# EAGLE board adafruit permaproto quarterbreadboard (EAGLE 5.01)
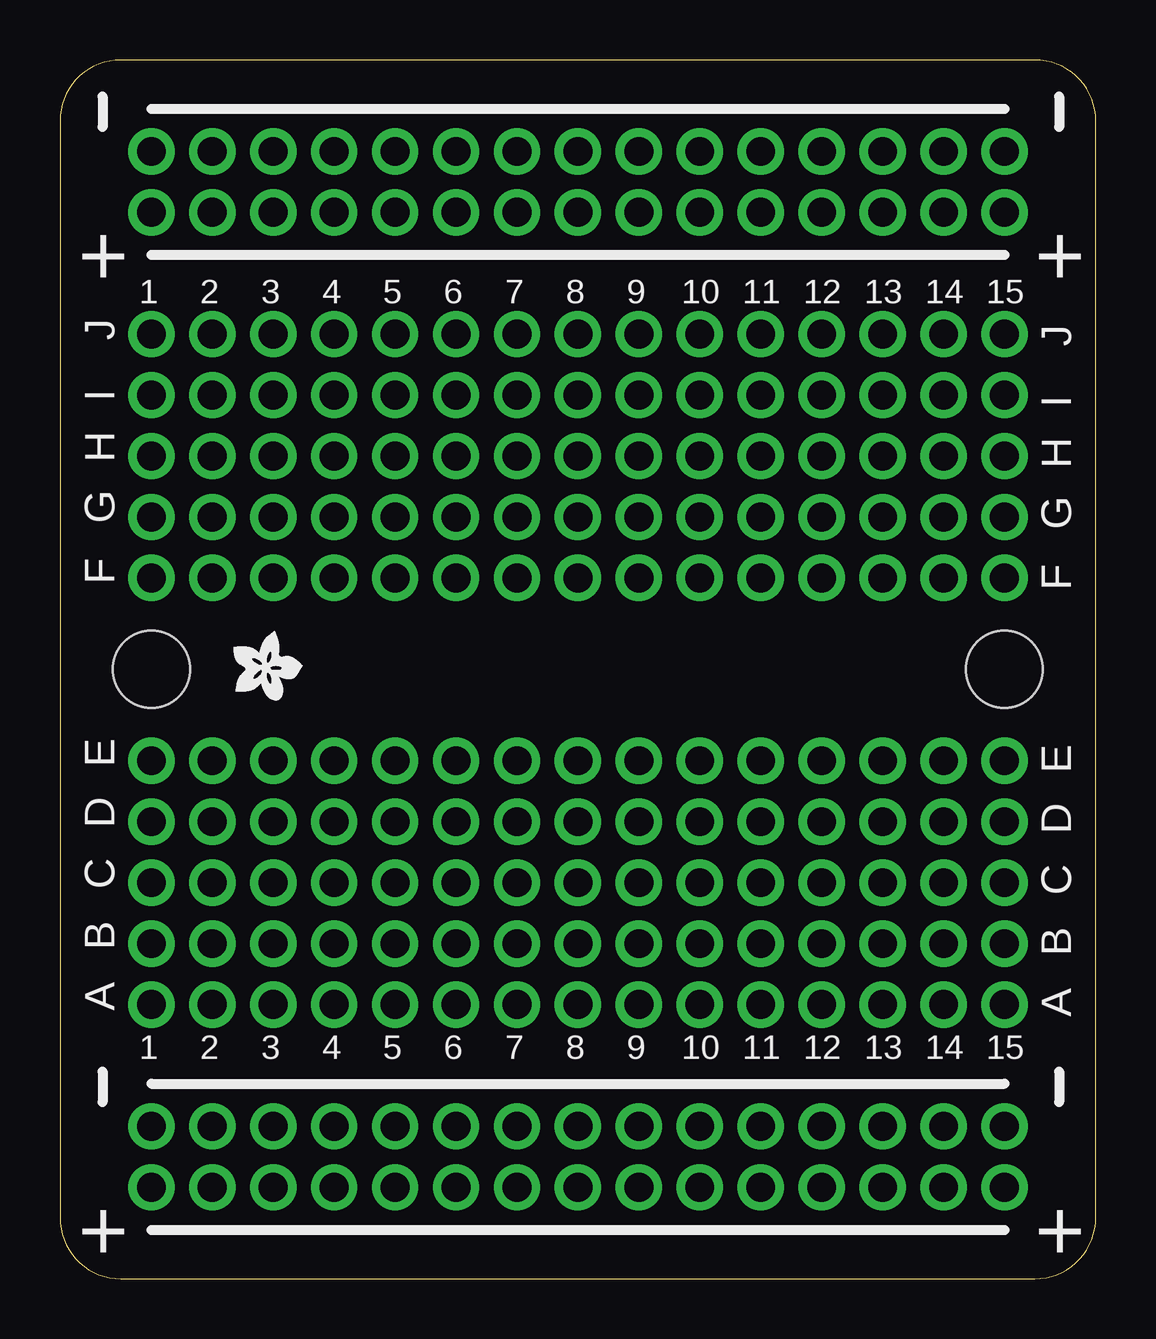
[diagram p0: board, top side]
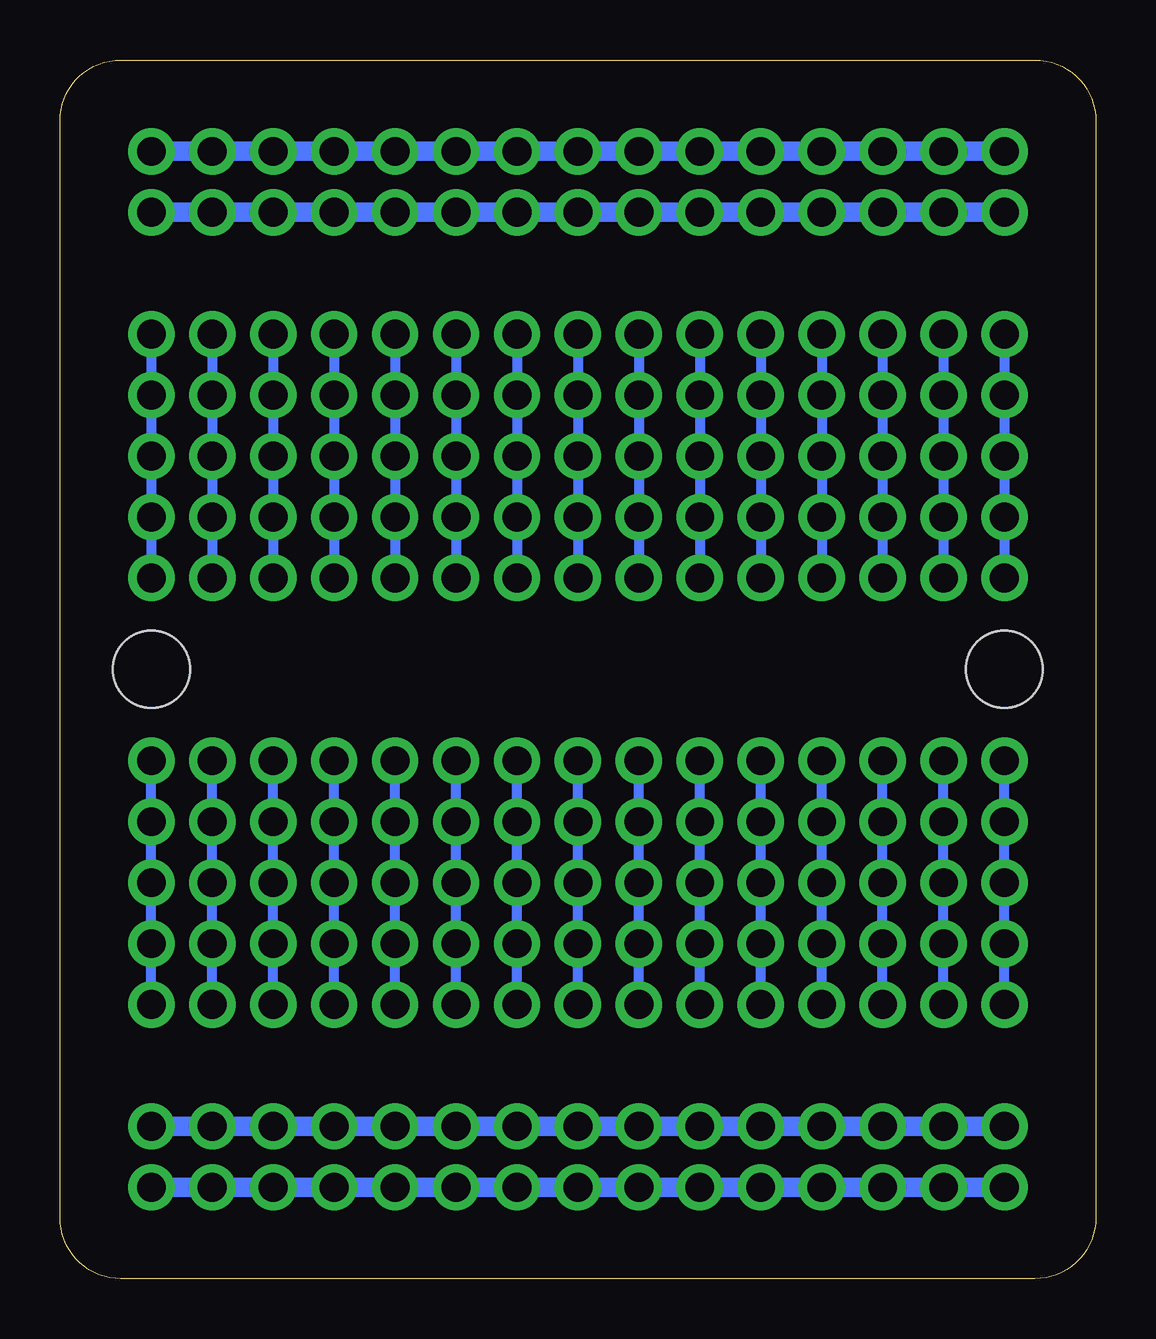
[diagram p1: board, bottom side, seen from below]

Size 43.18 x 50.8 mm. Coordinates in mm from the lower left corner, seen from the top.
Outline: 2.54,50.8 arc90 0,48.26 0,2.54 arc90 2.54,0 40.64,0 arc90 43.18,2.54 43.18,48.26 arc90 40.64,50.8 2.54,50.8
Copper layers (1*16): Top 0.035mm / dielectric 1.5mm / Bottom 0.035mm
Design rules "default": minimum track width 10mil, minimum drill 24mil, track to track 8mil, track to pad 8mil, pad to pad 8mil, via to via 8mil, smd to smd 8mil, copper to edge 40mil, drill to drill 8mil, minimum pad ring 10mil, minimum via ring 8mil, stop-mask expansion 4mil, vias tented up to drill 0mil, thermal gap 10mil
Holes 3.2 mm at 3.81,25.4 39.37,25.4

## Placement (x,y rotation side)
U$1  [ADAFRUIT200MIL]  8.64,25.65 270 top

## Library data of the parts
U$1 = adafruit

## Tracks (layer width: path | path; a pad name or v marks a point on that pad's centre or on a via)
N$1  (via drill 1.2 pad 1.93)
  Bottom 0.406: v3.81,21.59 v3.81,19.05 v3.81,16.51 v3.81,13.97 v3.81,11.43
N$2  (via drill 1.2 pad 1.93)
  Bottom 0.406: v6.35,11.43 v6.35,13.97 v6.35,16.51 v6.35,19.05 v6.35,21.59
N$3  (via drill 1.2 pad 1.93)
  Bottom 0.406: v8.89,21.59 v8.89,19.05 v8.89,16.51 v8.89,13.97 v8.89,11.43
N$4  (via drill 1.2 pad 1.93)
  Bottom 0.406: v11.43,11.43 v11.43,13.97 v11.43,16.51 v11.43,19.05 v11.43,21.59
N$5  (via drill 1.2 pad 1.93)
  Bottom 0.406: v13.97,21.59 v13.97,19.05 v13.97,16.51 v13.97,13.97 v13.97,11.43
N$6  (via drill 1.2 pad 1.93)
  Bottom 0.406: v16.51,11.43 v16.51,13.97 v16.51,16.51 v16.51,19.05 v16.51,21.59
N$7  (via drill 1.2 pad 1.93)
  Bottom 0.406: v21.59,11.43 v21.59,13.97 v21.59,16.51 v21.59,19.05 v21.59,21.59
N$8  (via drill 1.2 pad 1.93)
  Bottom 0.406: v19.05,21.59 v19.05,19.05 v19.05,16.51 v19.05,13.97 v19.05,11.43
N$9  (via drill 1.2 pad 1.93)
  Bottom 0.406: v24.13,21.59 v24.13,19.05 v24.13,16.51 v24.13,13.97 v24.13,11.43
N$10  (via drill 1.2 pad 1.93)
  Bottom 0.406: v26.67,21.59 v26.67,19.05 v26.67,16.51 v26.67,13.97 v26.67,11.43
N$11  (via drill 1.2 pad 1.93)
  Bottom 0.406: v29.21,21.59 v29.21,19.05 v29.21,16.51 v29.21,13.97 v29.21,11.43
N$12  (via drill 1.2 pad 1.93)
  Bottom 0.406: v31.75,11.43 v31.75,13.97 v31.75,16.51 v31.75,19.05 v31.75,21.59
N$13  (via drill 1.2 pad 1.93)
  Bottom 0.406: v34.29,21.59 v34.29,19.05 v34.29,16.51 v34.29,13.97 v34.29,11.43
N$14  (via drill 1.2 pad 1.93)
  Bottom 0.406: v36.83,11.43 v36.83,13.97 v36.83,16.51 v36.83,19.05 v36.83,21.59
N$15  (via drill 1.2 pad 1.93)
  Bottom 0.406: v39.37,11.43 v39.37,13.97 v39.37,16.51 | v39.37,16.51 v39.37,19.05 | v39.37,19.05 v39.37,21.59 | v39.37,16.51 v39.37,19.05
N$31  (via drill 1.2 pad 1.93)
  Bottom 0.813: v3.81,6.35 v6.35,6.35 v8.89,6.35 v11.43,6.35 v13.97,6.35 v16.51,6.35 v19.05,6.35 v21.59,6.35 v24.13,6.35 v26.67,6.35 v29.21,6.35 v31.75,6.35 v34.29,6.35 v36.83,6.35 v39.37,6.35
N$32  (via drill 1.2 pad 1.93)
  Bottom 0.813: v3.81,3.81 v6.35,3.81 v8.89,3.81 v11.43,3.81 v13.97,3.81 v16.51,3.81 v19.05,3.81 v21.59,3.81 v24.13,3.81 v26.67,3.81 v29.21,3.81 v31.75,3.81 v34.29,3.81 v36.83,3.81 v39.37,3.81
N$48  (via drill 1.2 pad 1.93)
  Bottom 0.406: v39.37,29.21 v39.37,31.75 v39.37,34.29 v39.37,36.83 v39.37,39.37
N$49  (via drill 1.2 pad 1.93)
  Bottom 0.406: v34.29,29.21 v34.29,31.75 v34.29,34.29 v34.29,36.83 v34.29,39.37
N$50  (via drill 1.2 pad 1.93)
  Bottom 0.406: v36.83,39.37 v36.83,36.83 v36.83,34.29 v36.83,31.75 v36.83,29.21
N$51  (via drill 1.2 pad 1.93)
  Bottom 0.406: v31.75,29.21 v31.75,31.75 v31.75,34.29 v31.75,36.83 v31.75,39.37
N$52  (via drill 1.2 pad 1.93)
  Bottom 0.406: v29.21,39.37 v29.21,36.83 v29.21,34.29 v29.21,31.75 v29.21,29.21
N$53  (via drill 1.2 pad 1.93)
  Bottom 0.406: v24.13,39.37 v24.13,36.83 v24.13,34.29 v24.13,31.75 v24.13,29.21
N$54  (via drill 1.2 pad 1.93)
  Bottom 0.406: v26.67,29.21 v26.67,31.75 v26.67,34.29 v26.67,36.83 v26.67,39.37
N$55  (via drill 1.2 pad 1.93)
  Bottom 0.406: v21.59,29.21 v21.59,31.75 v21.59,34.29 v21.59,36.83 v21.59,39.37
N$56  (via drill 1.2 pad 1.93)
  Bottom 0.406: v19.05,39.37 v19.05,36.83 v19.05,34.29 v19.05,31.75 v19.05,29.21
N$57  (via drill 1.2 pad 1.93)
  Bottom 0.406: v16.51,29.21 v16.51,31.75 v16.51,34.29 v16.51,36.83 v16.51,39.37
N$58  (via drill 1.2 pad 1.93)
  Bottom 0.406: v13.97,39.37 v13.97,36.83 v13.97,34.29 v13.97,31.75 v13.97,29.21
N$59  (via drill 1.2 pad 1.93)
  Bottom 0.406: v8.89,29.21 v8.89,31.75 v8.89,34.29 v8.89,36.83 v8.89,39.37
N$60  (via drill 1.2 pad 1.93)
  Bottom 0.406: v11.43,39.37 v11.43,36.83 v11.43,34.29 v11.43,31.75 v11.43,29.21
N$61  (via drill 1.2 pad 1.93)
  Bottom 0.406: v6.35,29.21 v6.35,31.75 v6.35,34.29 v6.35,36.83 v6.35,39.37
N$62  (via drill 1.2 pad 1.93)
  Bottom 0.406: v3.81,39.37 v3.81,36.83 v3.81,34.29 v3.81,31.75 v3.81,29.21
N$63  (via drill 1.2 pad 1.93)
  Bottom 0.813: v39.37,44.45 v36.83,44.45 v34.29,44.45 v31.75,44.45 | v29.21,44.45 v31.75,44.45 | v29.21,44.45 v26.67,44.45 v24.13,44.45 v21.59,44.45 v19.05,44.45 v16.51,44.45 v13.97,44.45 | v13.97,44.45 v11.43,44.45 | v11.43,44.45 v8.89,44.45 v6.35,44.45 v3.81,44.45 | v13.97,44.45 v11.43,44.45 | v29.21,44.45 v31.75,44.45
N$64  (via drill 1.2 pad 1.93)
  Bottom 0.813: v39.37,46.99 v36.83,46.99 v34.29,46.99 v31.75,46.99 | v29.21,46.99 v31.75,46.99 | v29.21,46.99 v26.67,46.99 v24.13,46.99 v21.59,46.99 v19.05,46.99 v16.51,46.99 v13.97,46.99 | v13.97,46.99 v11.43,46.99 | v11.43,46.99 v8.89,46.99 v6.35,46.99 v3.81,46.99 | v13.97,46.99 v11.43,46.99 | v29.21,46.99 v31.75,46.99

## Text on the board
tPlace: 1 | 2 | 3 | 4 | 5 | 6 | 7 | 8 | 9 | 10 | 11 | 12 | 13 | 14 | 15 | J | J | I | I | H | H | G | G | F | F | E | E | D | D | C | C | B | B | A | A | 1 | 2 | 3 | 4 | 5 | 6 | 7 | 8 | 9 | 10 | 11 | 12 | 13 | 14 | 15
tDocu: Adafruit Perma-Proto | 1/4 Sized Breadboard
tPlaceRed: + | + | + | +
